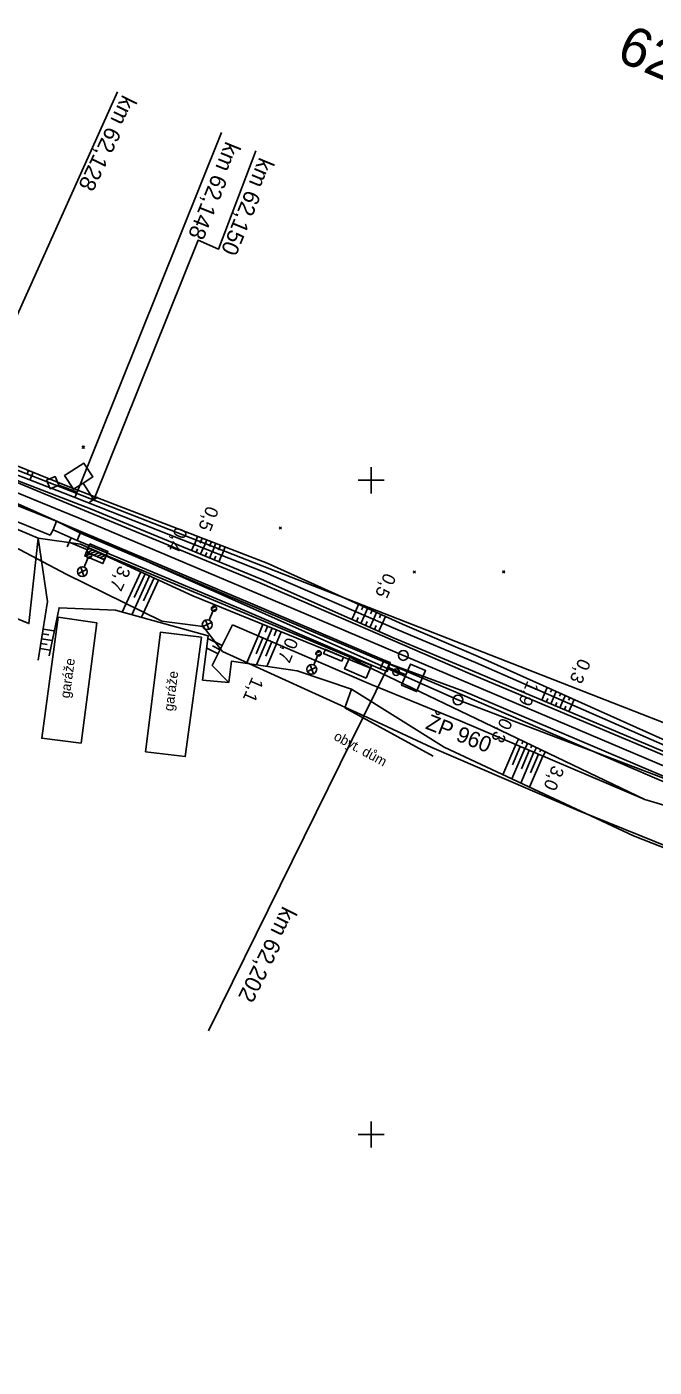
# Model space of a CAD drawing. Extents: x -805636 to -804553, y -1165340 to -1164656.
# Drawn here: x -805352.6 to -805256.7, y -1165035.6 to -1164830.7 of the extents above; entities that cross this region are included whole.
import ezdxf

# ---------------------------------------------------------------- set-up
doc = ezdxf.new("R2010")
doc.units = 0
for name, color, linetype in [('0381KM061-064P - Vrstva 1', 7, 'Continuous'), ('0381KM061-064P - Vrstva 13', 7, 'Continuous'), ('0381KM061-064P - Vrstva 14', 7, 'Continuous'), ('0381KM061-064P - Vrstva 16', 7, 'Continuous'), ('0381KM061-064P - Vrstva 17', 7, 'Continuous'), ('0381KM061-064P - Vrstva 23', 7, 'Continuous'), ('0381KM061-064P - Vrstva 25', 7, 'Continuous'), ('0381KM061-064P - Vrstva 4', 7, 'Continuous'), ('0381KM061-064P - Vrstva 48', 7, 'Continuous'), ('0381KM061-064P - Vrstva 49', 7, 'Continuous'), ('0381KM061-064P - Vrstva 7', 7, 'Continuous'), ('0381KM061-064P - Vrstva 8', 7, 'Continuous'), ('hran DP - hran DP', 7, 'Continuous'), ('krizky_1000 - Vrstva 1', 7, 'Continuous'), ('vyt_sit - polygon', 7, 'Continuous'), ('vyt_sit - stávající', 7, 'Continuous')]:
    doc.layers.add(name, color=color, linetype=linetype)

msp = doc.modelspace()

# ---------------------------------------------------------------- linework, layer by layer
at = {"layer": '0381KM061-064P - Vrstva 1'}
for points in [[(-805362.07, -1164898.64), (-805347.39, -1164904.64), (-805344.65, -1164905.78)], [(-805344.65, -1164905.78), (-805313.66, -1164918.88), (-805286.17, -1164930.55), (-805256.63, -1164943.09), (-805230.48, -1164954.2), (-805205.12, -1164965.01), (-805202.66, -1164966.06)]]:
    msp.add_lwpolyline(points, dxfattribs=at)
at = {"layer": '0381KM061-064P - Vrstva 13'}
msp.add_lwpolyline([(-805321.75, -1164930.89), (-805321.36, -1164927.66), (-805311.3, -1164929.13), (-805302.99, -1164931.92), (-805304.04, -1164934.8)], dxfattribs=at)
at = {"layer": '0381KM061-064P - Vrstva 14'}
for points in [[(-805348.61, -1164907.57), (-805344.97, -1164909.22), (-805344.37, -1164907.83), (-805348.12, -1164906.22)], [(-805298.03, -1164927.49), (-805318.81, -1164918.63), (-805344.37, -1164907.83)], [(-805344.97, -1164909.22), (-805319.37, -1164919.91), (-805298.61, -1164928.83), (-805298.03, -1164927.49)], [(-805298.03, -1164927.49), (-805297.09, -1164927.83), (-805297.56, -1164929.24), (-805298.61, -1164928.83)]]:
    msp.add_lwpolyline(points, dxfattribs=at)
at = {"layer": '0381KM061-064P - Vrstva 16'}
msp.add_lwpolyline([(-805366.38, -1164898.98), (-805348.12, -1164906.22), (-805348.61, -1164907.57), (-805349.09, -1164908.36), (-805367.46, -1164900.88), (-805366.38, -1164898.98)], dxfattribs=at)
at = {"layer": '0381KM061-064P - Vrstva 17'}
for points in [[(-805369.75, -1164914.7), (-805368.04, -1164901.63), (-805350.89, -1164908.84), (-805352.32, -1164921.91), (-805369.75, -1164914.7)], [(-805344.45, -1164909.76), (-805340.69, -1164911.4), (-805303.48, -1164926.91), (-805299.84, -1164928.84)]]:
    msp.add_lwpolyline(points, dxfattribs=at)
at = {"layer": '0381KM061-064P - Vrstva 23'}
for points in [[(-805344.35, -1164940.19), (-805350.35, -1164939.42), (-805347.83, -1164920.92), (-805341.94, -1164921.79), (-805344.35, -1164940.19)], [(-805334.52, -1164941.49), (-805332.2, -1164923.19), (-805325.94, -1164923.98), (-805328.43, -1164942.24), (-805334.52, -1164941.49)], [(-805304.04, -1164934.8), (-805290.52, -1164942.17)]]:
    msp.add_lwpolyline(points, dxfattribs=at)
for points in [[(-805304.5, -1164927.66), (-805304.24, -1164927.04), (-805306.99, -1164925.86), (-805307.26, -1164926.49)], [(-805300.76, -1164930.22), (-805304.05, -1164928.83), (-805303.22, -1164926.92), (-805299.93, -1164928.3)]]:
    msp.add_lwpolyline(points, close=True, dxfattribs=at)
at = {"layer": '0381KM061-064P - Vrstva 25'}
for p, q in [((-805343.87, -1164913.27), (-805343.29, -1164911.89)), ((-805342.87, -1164911.22), (-805343.53, -1164911.49)), ((-805342.74, -1164911.6), (-805343.35, -1164911.85)), ((-805343.5, -1164913.62), (-805344.84, -1164914.27)), ((-805343.92, -1164914.67), (-805344.41, -1164913.26)), ((-805324.77, -1164921.36), (-805324.19, -1164919.98)), ((-805323.78, -1164919.31), (-805324.43, -1164919.58)), ((-805323.65, -1164919.69), (-805324.26, -1164919.94)), ((-805324.4, -1164921.71), (-805325.74, -1164922.36)), ((-805324.83, -1164922.76), (-805325.31, -1164921.34)), ((-805308.78, -1164928.2), (-805308.19, -1164926.82)), ((-805307.78, -1164926.15), (-805308.43, -1164926.42)), ((-805307.64, -1164926.53), (-805308.26, -1164926.78)), ((-805308.41, -1164928.55), (-805309.75, -1164929.2)), ((-805308.83, -1164929.6), (-805309.31, -1164928.19))]:
    msp.add_line(p, q, dxfattribs=at)
for centre, radius in [((-805343.13, -1164911.52), 0.4), ((-805343.13, -1164911.52), 0.4), ((-805344.16, -1164913.96), 0.749), ((-805324.03, -1164919.61), 0.4), ((-805324.03, -1164919.61), 0.4), ((-805325.06, -1164922.05), 0.749), ((-805308.03, -1164926.45), 0.4), ((-805308.03, -1164926.45), 0.4), ((-805309.07, -1164928.89), 0.749)]:
    msp.add_circle(centre, radius, dxfattribs=at)
at = {"layer": '0381KM061-064P - Vrstva 4'}
for points in [[(-805364.7, -1164895.97), (-805343.19, -1164904.86), (-805317.03, -1164915.68), (-805296.75, -1164924.42), (-805284.83, -1164929.56), (-805254.7, -1164942.26), (-805226.16, -1164954.55), (-805203.52, -1164964.18), (-805187.57, -1164970.92)], [(-805364.7, -1164895.97), (-805342.91, -1164904.36), (-805316.81, -1164915.12), (-805296.46, -1164924.13), (-805284.52, -1164929.13), (-805254.45, -1164941.83), (-805225.92, -1164953.93), (-805203.38, -1164963.47), (-805187.4, -1164970.45)], [(-805348.12, -1164906.22), (-805344.46, -1164908.09), (-805318.48, -1164919.08), (-805298.17, -1164927.71), (-805286.08, -1164932.79)], [(-805298.17, -1164927.71), (-805285.87, -1164932.24)], [(-805286.08, -1164932.79), (-805257.4, -1164945.18)], [(-805285.87, -1164932.24), (-805257.21, -1164944.39)], [(-805257.4, -1164945.18), (-805227.5, -1164957.9), (-805205.55, -1164967.2), (-805161.7, -1164987.26), (-805121.4, -1165011.84), (-805082.08, -1165035.58)], [(-805257.21, -1164944.39), (-805227.21, -1164957.06), (-805205.17, -1164966.48), (-805161.59, -1164986.72), (-805120.84, -1165010.88), (-805082.03, -1165034.98)]]:
    msp.add_lwpolyline(points, dxfattribs=at)
at = {"layer": '0381KM061-064P - Vrstva 48'}
for p, q in [((-805352.38, -1164898.48), (-805352.62, -1164899.09)), ((-805351.69, -1164898.76), (-805352.17, -1164899.97)), ((-805327.03, -1164909.84), (-805326.53, -1164908.55)), ((-805327.08, -1164909.82), (-805327.46, -1164910.73)), ((-805326.54, -1164910.46), (-805326.77, -1164911.02)), ((-805326.13, -1164909.59), (-805325.83, -1164908.82)), ((-805325.69, -1164910.37), (-805326.07, -1164911.3)), ((-805325.63, -1164910.39), (-805325.13, -1164909.09)), ((-805324.73, -1164910.14), (-805324.43, -1164909.36)), ((-805324.24, -1164910.94), (-805323.73, -1164909.62)), ((-805323.34, -1164910.68), (-805323.04, -1164909.89)), ((-805322.84, -1164911.49), (-805322.34, -1164910.16)), ((-805325.14, -1164911.02), (-805325.38, -1164911.59)), ((-805324.29, -1164910.92), (-805324.69, -1164911.88)), ((-805323.75, -1164911.58), (-805323.99, -1164912.16)), ((-805322.9, -1164911.47), (-805323.3, -1164912.45)), ((-805338.05, -1164920.13), (-805335.23, -1164913.99)), ((-805336.59, -1164920.54), (-805333.87, -1164914.62)), ((-805336.21, -1164917.92), (-805334.55, -1164914.3)), ((-805335.12, -1164920.94), (-805332.51, -1164915.25)), ((-805334.79, -1164918.42), (-805333.19, -1164914.93)), ((-805302.93, -1164921.26), (-805302.4, -1164920.06)), ((-805301.91, -1164918.97), (-805302.4, -1164920.06)), ((-805301.56, -1164921.87), (-805301.02, -1164920.66)), ((-805301.23, -1164919.28), (-805301.47, -1164919.82)), ((-805300.54, -1164919.59), (-805301.03, -1164920.66)), ((-805299.86, -1164919.9), (-805300.1, -1164920.43)), ((-805299.18, -1164920.21), (-805299.65, -1164921.25)), ((-805298.49, -1164920.52), (-805298.73, -1164921.03)), ((-805297.81, -1164920.83), (-805298.27, -1164921.85)), ((-805348.46, -1164923.02), (-805350.15, -1164922.74)), ((-805316.54, -1164922.03), (-805317.26, -1164923.8)), ((-805315.84, -1164922.32), (-805316.21, -1164923.21)), ((-805315.15, -1164922.6), (-805315.88, -1164924.4)), ((-805314.45, -1164922.88), (-805314.82, -1164923.79)), ((-805302.24, -1164921.57), (-805301.98, -1164920.96)), ((-805300.87, -1164922.17), (-805300.6, -1164921.56)), ((-805300.19, -1164922.48), (-805299.64, -1164921.25)), ((-805299.5, -1164922.78), (-805299.23, -1164922.17)), ((-805298.81, -1164923.08), (-805298.27, -1164921.85)), ((-805349.55, -1164925.11), (-805350.5, -1164924.96)), ((-805348.76, -1164924.48), (-805350.38, -1164924.22)), ((-805349.27, -1164923.64), (-805350.26, -1164923.48)), ((-805324.95, -1164924.17), (-805322.77, -1164925.24)), ((-805319.05, -1164928), (-805317.25, -1164923.81)), ((-805317.59, -1164926.51), (-805316.56, -1164924.1)), ((-805317.51, -1164928.22), (-805315.87, -1164924.4)), ((-805316.12, -1164926.88), (-805315.18, -1164924.7)), ((-805315.97, -1164928.45), (-805314.49, -1164924.99)), ((-805313.76, -1164923.17), (-805314.5, -1164924.99)), ((-805349.06, -1164925.95), (-805350.62, -1164925.69)), ((-805325.14, -1164925.67), (-805323.4, -1164926.53)), ((-805324.26, -1164925.3), (-805323.09, -1164925.89)), ((-805273.91, -1164933.61), (-805273.44, -1164932.5)), ((-805273.06, -1164931.69), (-805273.43, -1164932.51)), ((-805272.38, -1164932), (-805272.56, -1164932.4)), ((-805272.52, -1164934.2), (-805272.06, -1164933.1)), ((-805271.7, -1164932.3), (-805272.05, -1164933.11)), ((-805271.01, -1164932.61), (-805271.19, -1164933.01)), ((-805270.33, -1164932.92), (-805270.68, -1164933.71)), ((-805273.21, -1164933.9), (-805272.98, -1164933.35)), ((-805271.83, -1164934.49), (-805271.6, -1164933.95)), ((-805271.14, -1164934.78), (-805270.69, -1164933.7)), ((-805270.45, -1164935.07), (-805270.23, -1164934.54)), ((-805269.64, -1164933.23), (-805269.82, -1164933.62)), ((-805269.76, -1164935.36), (-805269.31, -1164934.31)), ((-805268.96, -1164933.53), (-805269.31, -1164934.31)), ((-805279.84, -1164945.01), (-805277.88, -1164940.4)), ((-805278.48, -1164945.65), (-805276.5, -1164940.98)), ((-805278.37, -1164943.48), (-805277.19, -1164940.69)), ((-805277.44, -1164939.56), (-805277.85, -1164940.41)), ((-805277.01, -1164944.09), (-805275.81, -1164941.28)), ((-805276.76, -1164939.88), (-805276.96, -1164940.29)), ((-805276.09, -1164940.21), (-805276.46, -1164941)), ((-805275.41, -1164940.53), (-805275.59, -1164940.91)), ((-805274.73, -1164940.85), (-805275.08, -1164941.58)), ((-805274.06, -1164941.18), (-805274.22, -1164941.53)), ((-805277.12, -1164946.29), (-805275.12, -1164941.57)), ((-805275.77, -1164946.92), (-805273.74, -1164942.16)), ((-805275.64, -1164944.71), (-805274.43, -1164941.86)), ((-805273.38, -1164941.5), (-805273.7, -1164942.17))]:
    msp.add_line(p, q, dxfattribs=at)
at = {"layer": '0381KM061-064P - Vrstva 49'}
for p, q in [((-805343.83, -1164895.11), (-805344.18, -1164894.75)), ((-805343.83, -1164894.75), (-805344.18, -1164895.11)), ((-805313.7, -1164907.45), (-805314.05, -1164907.1)), ((-805313.7, -1164907.1), (-805314.05, -1164907.45)), ((-805293.23, -1164914.18), (-805293.58, -1164913.83)), ((-805293.23, -1164913.83), (-805293.58, -1164914.18)), ((-805279.54, -1164914.16), (-805279.9, -1164913.81)), ((-805279.54, -1164913.81), (-805279.9, -1164914.16))]:
    msp.add_line(p, q, dxfattribs=at)
for points in [[(-805364.02, -1164893.8), (-805346.07, -1164901.02), (-805315.87, -1164912.66), (-805295.19, -1164922.01)], [(-805366.61, -1164894.35), (-805364.7, -1164895.97), (-805342.91, -1164904.36), (-805316.81, -1164915.12), (-805296.46, -1164924.13)], [(-805364.49, -1164895.2), (-805347.1, -1164901.93), (-805316.44, -1164914.01), (-805295.94, -1164922.85)], [(-805350.89, -1164908.84), (-805349.46, -1164918.54)], [(-805350.89, -1164908.84), (-805344.45, -1164909.76), (-805327.24, -1164917.67), (-805299.84, -1164928.84), (-805258.14, -1164948.79)], [(-805350.92, -1164927.51), (-805349.46, -1164918.54)], [(-805349.24, -1164926.82), (-805347.72, -1164919.48), (-805339.1, -1164919.84), (-805324.89, -1164923.77)], [(-805321.75, -1164930.89), (-805324.29, -1164928.33), (-805321.22, -1164922.1)], [(-805299.97, -1164931.23), (-805321.22, -1164922.1)], [(-805295.94, -1164922.85), (-805284.04, -1164927.86), (-805253.46, -1164941.25), (-805223.68, -1164953.23)], [(-805295.19, -1164922.01), (-805283.65, -1164926.95), (-805253.5, -1164940.46), (-805223.68, -1164953.23)], [(-805324.89, -1164923.77), (-805325.79, -1164930.57)], [(-805296.46, -1164924.13), (-805284.52, -1164929.13), (-805254.45, -1164941.83), (-805225.92, -1164953.93)], [(-805321.75, -1164930.89), (-805321.36, -1164927.66), (-805311.3, -1164929.13), (-805302.99, -1164931.92)], [(-805321.75, -1164930.89), (-805325.79, -1164930.57)], [(-805302.99, -1164931.92), (-805288.85, -1164940.8), (-805259.86, -1164954.37)], [(-805299.97, -1164931.23), (-805286.39, -1164936.78), (-805258.14, -1164948.79)], [(-805258.14, -1164948.79), (-805227.5, -1164957.9)], [(-805259.86, -1164954.37), (-805233.78, -1164964.57)]]:
    msp.add_lwpolyline(points, dxfattribs=at)
at = {"layer": '0381KM061-064P - Vrstva 7'}
for p, q in [((-805343.05, -1164903.36), (-805341.79, -1164902.55)), ((-805297.43, -1164928.54), (-805324.84, -1164984.17)), ((-805297.14, -1164927.85), (-805297.72, -1164929.23)), ((-805296.2, -1164929.3), (-805296.11, -1164929.34))]:
    msp.add_line(p, q, dxfattribs=at)
for points in [[(-805342.42, -1164902.96), (-805326.45, -1164863.29), (-805323.31, -1164864.66), (-805317.63, -1164849.64)], [(-805342.42, -1164902.96), (-805344.04, -1164900.43), (-805342.56, -1164899.49), (-805343.91, -1164897.38), (-805346.86, -1164899.27), (-805345.51, -1164901.37), (-805344.04, -1164900.43)], [(-805297.43, -1164928.54), (-805294.67, -1164929.71), (-805295.35, -1164931.32), (-805293.05, -1164932.3), (-805291.68, -1164929.08), (-805293.98, -1164928.1), (-805294.67, -1164929.71)]]:
    msp.add_lwpolyline(points, dxfattribs=at)
for centre, radius in [((-805295.08, -1164926.77), 0.75), ((-805296.16, -1164929.32), 0.5)]:
    msp.add_circle(centre, radius, dxfattribs=at)
at = {"layer": '0381KM061-064P - Vrstva 8'}
for p, q in [((-805363.02, -1164894.54), (-805338.8, -1164840.62)), ((-805344.97, -1164901.83), (-805322.86, -1164846.82)), ((-805345.25, -1164902.52), (-805344.69, -1164901.13)), ((-805345.86, -1164908.78), (-805346.45, -1164910.16)), ((-805343.41, -1164911.01), (-805342.5, -1164910.64)), ((-805343.37, -1164910.58), (-805342.99, -1164910.43)), ((-805342.92, -1164911.21), (-805342.01, -1164910.84)), ((-805342.44, -1164911.42), (-805341.52, -1164911.05)), ((-805341.95, -1164911.63), (-805341.03, -1164911.26)), ((-805341.46, -1164911.83), (-805340.55, -1164911.46)), ((-805340.97, -1164912.04), (-805340.68, -1164911.92))]:
    msp.add_line(p, q, dxfattribs=at)
for points in [[(-805344.97, -1164901.83), (-805347.76, -1164900.72), (-805349.06, -1164901.28), (-805349.62, -1164899.98), (-805348.32, -1164899.42), (-805347.76, -1164900.72)], [(-805343.39, -1164910.63), (-805346.15, -1164909.47)], [(-805343, -1164909.72), (-805340.24, -1164910.88), (-805341.02, -1164912.73), (-805343.78, -1164911.56), (-805343, -1164909.72)]]:
    msp.add_lwpolyline(points, dxfattribs=at)
msp.add_lwpolyline([(-805343.26, -1164910.32), (-805340.49, -1164911.48), (-805340.76, -1164912.13), (-805343.53, -1164910.96)], close=True, dxfattribs=at)
at = {"layer": 'hran DP - hran DP'}
for p, q in [((-805367.78, -1164893.1), (-805249.75, -1164939.24)), ((-805346.65, -1164914.36), (-805367.9, -1164903.11)), ((-805332.02, -1164921.55), (-805346.65, -1164914.36)), ((-805325.7, -1164922.37), (-805332.02, -1164921.55)), ((-805322.74, -1164926.15), (-805325.7, -1164922.37)), ((-805300.55, -1164936.27), (-805322.74, -1164926.15)), ((-805290.72, -1164940.83), (-805300.55, -1164936.27)), ((-805268.35, -1164950.48), (-805290.72, -1164940.83)), ((-805235.86, -1164963.58), (-805268.35, -1164950.48))]:
    msp.add_line(p, q, dxfattribs=at)
at = {"layer": 'krizky_1000 - Vrstva 1'}
for points in [[(-805300, -1164898), (-805300, -1164902)], [(-805302, -1164900), (-805298, -1164900)], [(-805300, -1164998), (-805300, -1165002)], [(-805302, -1165000), (-805298, -1165000)]]:
    msp.add_lwpolyline(points, dxfattribs=at)
at = {"layer": 'vyt_sit - polygon'}
for p, q in [((-805286.72, -1164933.58), (-805412.1, -1164877.75)), ((-805156.24, -1164983.18), (-805286.72, -1164933.58))]:
    msp.add_line(p, q, dxfattribs=at)
at = {"layer": 'vyt_sit - stávající'}
msp.add_line((-805286.76, -1164933.55), (-805286.68, -1164933.61), dxfattribs=at)
msp.add_circle((-805286.72, -1164933.58), 0.756, dxfattribs=at)

# ---------------------------------------------------------------- texts
at = {"layer": '0381KM061-064P - Vrstva 23'}
for s, rotation, p in [('garáže', 82.2322, (-805346.1, -1164933.37)), ('garáže', 82.7783, (-805330.26, -1164935.34)), (' obyt. dům', 331.3934, (-805306.33, -1164939.31))]:
    msp.add_text(s, height=1.5, rotation=rotation, dxfattribs=at).set_placement(p)
at = {"layer": '0381KM061-064P - Vrstva 48'}
for s, rotation, p in [('0,5', 248.495, (-805325.1, -1164903.79)), ('0,4', 247.5875, (-805329.86, -1164906.99)), ('3,7', 245.3182, (-805338.51, -1164912.91)), ('0,5', 245.6505, (-805297.92, -1164914.02)), ('0,7', 247.8034, (-805312.93, -1164923.87)), ('0,3', 245.8554, (-805268.17, -1164927.09)), ('1,1', 246.7728, (-805318.19, -1164929.95)), ('1,9', 247.0941, (-805276.08, -1164930.53)), ('0,3', 244.4427, (-805280.1, -1164936.16)), ('3,0', 246.9723, (-805272.24, -1164943.45))]:
    msp.add_text(s, height=2, rotation=rotation, dxfattribs=at).set_placement(p)
at = {"layer": '0381KM061-064P - Vrstva 7'}
for s, height, rotation, p in [('62,2', 6, 337.0034, (-805262.71, -1164835.71)), ('km 62,150', 2.5, 247.6272, (-805317.06, -1164850.49)), ('km 62,202', 2.5, 243.7716, (-805313.5, -1164964.97))]:
    msp.add_text(s, height=height, rotation=rotation, dxfattribs=at).set_placement(p)
at = {"layer": '0381KM061-064P - Vrstva 8'}
for s, rotation, p in [('km 62,128', 244.0036, (-805337.99, -1164840.93)), ('km 62,148', 248.1034, (-805322.21, -1164848.06))]:
    msp.add_text(s, height=2.5, rotation=rotation, dxfattribs=at).set_placement(p)
at = {"layer": 'vyt_sit - stávající'}
msp.add_text('ŽP 960', height=2.4, rotation=338.5611, dxfattribs=at).set_placement((-805291.82, -1164937.92))

doc.saveas('drawing.dxf')
